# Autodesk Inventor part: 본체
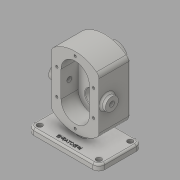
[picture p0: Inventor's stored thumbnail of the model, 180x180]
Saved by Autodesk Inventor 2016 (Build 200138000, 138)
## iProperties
Created: 2019-03
Part Number: 본체
Material: Generic
Document SubType Name: Modeling
Designer: Administrator
Density: 1 g/cm^3
Appearance: Default
Author: Administrator
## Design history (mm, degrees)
sketch "스케치1"
  geometry: L1 (60, -36.5)-(-60, -36.5); L2 (-60, -36.5)-(-60, 36.5); L3 (-60, 36.5)-(60, 36.5); L4 (60, 36.5)-(60, -36.5); L5 (60, -36.5)-(-60, 36.5); L6 (-60, -36.5)-(60, 36.5); 1 further point
  constraints: 12 end point, 2 midpoint, 2 parallel, 1 horizontal, 1 perpendicular
  dimensions: "d0" = 120 distance of L1.start L1.end; "d1" = 73 distance of L1.end L2.end
extrude "돌출1" new body sketch "스케치1" distance "d2" = 10; taper "d3" = 0 deg
fillet "모깎기1" dims "d4" = 10
sketch "스케치2"
  geometry: 1 further point
sketch "스케치3"
  geometry: L1 (50, 36.5)-(-50, 36.5) reference; L2 (0, 0)-(0, 36.5); L3 (-6, -6.5)-(6, -6.5); L4 (6, -6.5)-(6, 36.5); L5 (6, 36.5)-(-6, 36.5); L6 (-6, 36.5)-(-6, -6.5); 1 further point
  constraints: 10 end point, 3 midpoint, 2 parallel, 1 horizontal, 1 perpendicular
  dimensions: "d42" = 12 distance of L3.start L3.end; "d43" = 43 distance of L3.end L4.end
extrude "돌출2" join sketch "스케치3" distance "d44" = 78; taper "d45" = 0 deg
fillet "모깎기3" dims "d46" = 3
sketch "스케치4"
  geometry: L1 (10, 66)-(90, 66); L2 (90, 66)-(90, 110); L3 (90, 110)-(10, 110); L4 (10, 110)-(10, 66); L5 (56, 88)-(44, 88) reference; L6 (10, 66)-(90, 110); L7 (90, 66)-(10, 110); L8 (50, 0)-(50, 138); L9 (50, 138)-(61.235, 138); L10 (10, 110)-(10, 122.721); L11 (90, 110)-(90, 122.721); L12 (10, 66)-(-38.552, 66); L13 (90, 66)-(122.984, 66); A1 r 60 centre (50, 78) between (90, 122.721) and (10, 122.721); 1 further point
  constraints: 24 end point, 4 horizontal, 3 midpoint, 3 point on circle, 3 vertical, 2 parallel, 1 centre point, 1 perpendicular, 1 point on line, 1 tangent
  dimensions: "d47" = 44 distance of L1.end L2.end; "d48" = 80 distance of L2.end L3.end; "d49" = 138 distance of L8.start L8.end; "d51" = 60 radius of A1
extrude "돌출3" join sketch "스케치4" distance "d52" = 53; taper "d53" = 0 deg
node "작업 평면1"
sketch "스케치7"
  geometry: L1 (-50, 100)-(-50, 56); L2 (-50, 100)-(-50, 56); L3 (-74, 100)-(-74, 56); L4 (-26, 56)-(-26, 100); A1 r 60 centre (-50, 78) between (-10, 122.721) and (-90, 122.721) reference; A2 r 24 centre (-50, 100) between (-26, 100) and (-74, 100); A3 r 24 centre (-50, 56) between (-74, 56) and (-26, 56); 3 further points
  constraints: 10 end point, 4 point on circle, 4 tangent, 2 centre point, 2 midpoint, 2 vertical, 1 coincident, 1 parallel
  dimensions: "d55" = 44 distance of L1.start L1.end; "d56" = 24 radius of A2
extrude "돌출4" cut sketch "스케치7" distance "d57" = 29; taper "d58" = 0 deg
fillet "모깎기4" dims "d59" = 10
sketch "스케치8"
  geometry: L1 (90, 38)-(90, 118) reference; L2 (10, 38)-(10, 118) reference; L3 (44, 7)-(44, 18.301) reference; L4 (0, 7)-(44, 7) reference; L5 (0, 0)-(0, 7) reference; L6 (100, 0)-(0, 0) reference; L7 (100, 7)-(100, 0) reference; L8 (56, 7)-(100, 7) reference; L9 (56, 18.301)-(56, 7) reference; C1 r 19 at (50, 100); A1 r 10 centre (80, 38) between (86, 30) and (90, 38) reference; A2 r 10 centre (80, 118) between (90, 118) and (86, 126) reference; A3 r 60 centre (50, 78) between (86, 126) and (14, 126) reference; A4 r 10 centre (20, 118) between (14, 126) and (10, 118) reference; A5 r 10 centre (20, 38) between (10, 38) and (14, 30) reference; A6 r 60 centre (50, 78) between (14, 30) and (44, 18.301) reference; A7 r 60 centre (50, 78) between (56, 18.301) and (86, 30) reference; A8 r 24 centre (50, 100) between (74, 100) and (26, 100) reference; 1 further point
  constraints: 1 centre point, 1 coincident
  dimensions: "d60" = 38 diameter of C1
extrude "돌출5" join sketch "스케치8" distance "d61" = 17; taper "d62" = 0 deg
fillet "모깎기5" dims "d63" = 3
hole "구멍5" diameter "d66" = 17; stored, may be unused: countersink angle "d70" = 90 deg, drill point angle "d72" = 118 deg; dims "d64" = 10, "d65" = 10, "d67" = 6, "d68" = 28, "d69" = 7.3, "d71" = 8
fillet "모깎기6" dims "d73" = 0.3
sketch "스케치9"
  geometry: L1 (114, -52.8)-(114.404, -53.5); L2 (81, -53.5)-(119, -53.5) reference; L3 (114, -46.5)-(114, -53.5) reference; L4 (114.404, -53.5)-(114, -53.5); L5 (114, -53.5)-(114, -52.8); L6 (91.5, -46.2)-(108.5, -46.2) reference; L7 (100, -46.2)-(100, -61.618); 1 further point
  constraints: 8 end point, 2 collinear, 1 midpoint, 1 point on line, 1 vertical
  dimensions: "d74" = 0.7 distance from line of L2 L1.start; "d75" = 30 deg angle of L3 L1
revolve "회전1" sketch "스케치9" stored, may be unused: angle "d76" = 90 deg
hole "구멍6" diameter "d79" = 25; stored, may be unused: countersink angle "d83" = 90 deg, drill point angle "d85" = 0 deg; dims "d77" = 10, "d78" = 10, "d80" = 6, "d81" = 28, "d82" = 7.3, "d84" = 15
hole "구멍7" diameter "d88" = 25; stored, may be unused: countersink angle "d92" = 90 deg, drill point angle "d94" = 0 deg; dims "d86" = 10, "d87" = 10, "d89" = 6, "d90" = 28, "d91" = 7.3, "d93" = 15
sketch "스케치11"
  geometry: L1 (-53, 80)-(-53, 0) reference; L2 (-53, 40)-(-39, 40); L3 (-10, -38)-(-63, -38) reference; C1 r 11 at (-39, 40); 1 further point
  constraints: 2 end point, 1 centre point, 1 coincident, 1 horizontal, 1 midpoint
  dimensions: "d95" = 14 distance of L2.start L2.end; "d96" = 78 distance between parallel lines of L3 L2; "d97" = 22 diameter of C1
extrude "돌출6" join sketch "스케치11" distance "d98" = 8; taper "d99" = 0 deg
fillet "모깎기7" dims "d100" = 3
fillet "모깎기8" dims "d101" = 3
hole "구멍8" diameter "d104" = 8.376; stored, may be unused: countersink angle "d108" = 90 deg, drill point angle "d110" = 0 deg; dims "d105" = 20, "d106" = 28, "d107" = 7.3, "d109" = 27.3, "d130" = 10, "d131" = 10
chamfer "모따기1" distance "d111" = 1; stored, may be unused: second distance "d112" = 2, angle "d113" = 45 deg
fillet "모깎기9" dims "d114" = 3
fillet "모깎기10" dims "d115" = 3
sketch "스케치13"
  geometry: L1 (-90, 78)-(-10, 78); L2 (-50, 56)-(-50, 100); L3 (-19, 56)-(-19, 100); L4 (-81, 100)-(-81, 56); L5 (-50, 78)-(-50, 100); L6 (-50, 100)-(-19, 100); L7 (-50, 100)-(-81, 100); L8 (-50, 100)-(-50, 131); L9 (-90, 118)-(-90, 78) reference; L10 (-10, 118)-(-10, 78) reference; L11 (0, 0)-(-100, 0) reference; C1 r 13.5 at (-50, 100) reference; A1 r 31 centre (-50, 56) between (-81, 56) and (-19, 56); A2 r 31 centre (-50, 100) between (-19, 100) and (-81, 100); 1 further point
  constraints: 18 end point, 5 point on circle, 4 tangent, 2 centre point, 2 midpoint, 1 parallel, 1 point on line, 1 vertical
  dimensions: "d116" = 31 radius of A2; "d117" = 22 distance of L5.start L5.end; "d125" = 78 distance between parallel lines of L11 L1
hole "구멍9" sketch "스케치13" at (-50, 131), (-81, 100), (-19, 100) diameter "d118" = 4.134; stored, may be unused: countersink angle "d122" = 90 deg, drill point angle "d124" = 118 deg; dims "d119" = 10, "d120" = 28, "d121" = 7.3, "d123" = 12
sketch "스케치14"
  geometry: L1 (-50, -36.5)-(50, -36.5) reference; L2 (-60, 26.5)-(-60, -26.5) reference; 2 further points
  constraints: 1 other
  dimensions: "d126" = 10 distance from line of L1 point (0, -26.5); "d127" = 60 distance from line of L2 point (0, -26.5)
feature "엠보싱1" sketch "스케치14" dims "d43" = 43, "d128" = 0.5, "d129" = 0
hole "구멍10" diameter "d134" = 9; stored, may be unused: countersink angle "d138" = 90 deg, drill point angle "d140" = 118 deg; dims "d132" = 10, "d133" = 10, "d135" = 10, "d136" = 28, "d137" = 7.3, "d139" = 12
hole "구멍11" diameter "d143" = 9; stored, may be unused: countersink angle "d147" = 90 deg, drill point angle "d149" = 118 deg; dims "d141" = 10, "d142" = 10, "d144" = 10, "d145" = 28, "d146" = 7.3, "d148" = 12
hole "구멍12" diameter "d152" = 9; stored, may be unused: countersink angle "d156" = 90 deg, drill point angle "d158" = 118 deg; dims "d150" = 10, "d151" = 10, "d153" = 10, "d154" = 28, "d155" = 7.3, "d157" = 12
hole "구멍13" diameter "d161" = 9; stored, may be unused: countersink angle "d165" = 90 deg, drill point angle "d167" = 118 deg; dims "d159" = 10, "d160" = 10, "d162" = 10, "d163" = 28, "d164" = 7.3, "d166" = 12
node "솔리드1"
mirror "대칭1"
mirror "대칭2"
mirror "대칭3"
node "투영된 루프1"
other parameters: "d54" = 78
